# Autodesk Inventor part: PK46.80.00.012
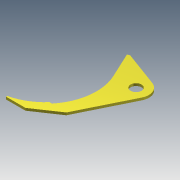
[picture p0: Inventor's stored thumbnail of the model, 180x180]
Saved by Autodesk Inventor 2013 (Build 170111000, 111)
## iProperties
Shininess: 64.0
Length Units: 11269
Angle Units: 11279
Time Units: 11290
Mass Units: 11283
Length Display Precision: 3
Angle Display Precision: 2
Compacted: True
Part Number: PK46.80.00.012
Document SubType Name: Modeling
Created: 2005-01
Material: Steel, Mild
Designer: SAlex
Manufacturer: Standard
Standards Organization: Custom
Density: 7.86 g/cm^3
Mass: 20735.7 g
Surface Area: 3167.75 cm^2
Volume: 2638.13 cm^3
Density: 0.0
Volumn: 0.0
Area: 0.0
PropertySet Name: Model Information
Control State: 0
Master: False
Checked Out: False
Checked Out Date: 2008-10-15
Last Check In Date: 2008-10-15
Author: SAlex
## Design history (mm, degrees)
sketch "Sketch1"
  geometry: L1 (-250.055, 155.763)-(-231.929, 164.216); L2 (-231.929, 164.216)-(59.267, 56.613); L3 (-209.127, -500.563)-(-230.09, -500.563); L4 (-250.055, 155.763)-(-152.853, -52.687); L5 (117.157, -88.09)-(-87.127, -504.878); L6 (-87.127, -504.878)-(-287.127, -639.878); L7 (-287.127, -639.878)-(-447.127, -639.878); L8 (-447.127, -639.878)-(-447.127, -629.827); L9 (-537.127, -231.878)-(-152.853, -52.687); C1 r 45 at (22.873, -41.878); A1 r 105 centre (22.873, -41.878) between (117.157, -88.09) and (59.267, 56.613); A2 r 424 centre (-537.127, -231.878) between (-209.127, -500.563) and (-152.853, -52.687); A3 r 408 centre (-537.127, -231.878) between (-447.127, -629.827) and (-230.09, -500.563)
  constraints: 18 end point, 6 point on circle, 4 centre point, 3 perpendicular, 3 tangent, 2 coincident, 1 horizontal, 1 parallel, 1 other
  dimensions: "d0" = 90 diameter of C1; "d8" = 424 radius of A2; "d25" = 105 radius of A1; "d35" = 230 distance of L1.start L4.end; "d36" = 232 horizontal distance of L3.start C1.centre; "d37" = 408 radius of A3; "d41" = 135 vertical distance of L5.end L6.end; "d42" = 90 distance from line of A2.centre L8; "d43" = 190 vertical distance of C1.centre A2.centre; "d44" = 20 distance of L1.start L1.end; "d45" = 560 horizontal distance of C1.centre A2.centre; "d46" = 408 distance from line of A2.centre L7; "d47" = 450 horizontal distance of A2.centre L5.end; "d48" = 160 distance of L6.end L7.end; "d49" = 115 deg angle of L9 L8
extrude "Extrusion1" new body sketch "Sketch1" distance "d9" = 20; taper "d10" = 0 deg
body "Solid1"
